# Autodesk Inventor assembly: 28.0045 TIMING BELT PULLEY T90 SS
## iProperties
Created: 2007-04
Part Number: 28.0045 TIMING BELT PULLEY T90 SS
Document SubType Name: Assembly
Designer: Andy Moles
Author: Andy Moles
